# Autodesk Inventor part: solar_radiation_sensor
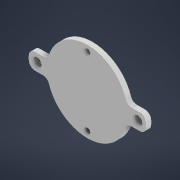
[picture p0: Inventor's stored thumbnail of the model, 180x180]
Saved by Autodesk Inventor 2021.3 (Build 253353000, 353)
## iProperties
Created: 2022-08
Part Number: solar_radiation_sensor
Material: Generisch
Document SubType Name: Modeling
Designer: markus.rampp
Density: 1 g/cm^3
Appearance: Vorgabe
Author: markus.rampp
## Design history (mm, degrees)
sketch "Skizze1"
  geometry: C1 r 40 at (0, 0); C2 r 2.8 at (0, 34); C3 r 2.8 at (0, -34); 1 further point
  constraints: 3 centre point, 2 vertical alignment, 1 coincident
  dimensions: "d20" = 80 diameter of C1; "d21" = 5.6 diameter of C2; "d22" = 5.6 diameter of C3 (= d21); "d23" = 68 distance of C3.centre C2.centre; "d24" = 34 distance of C1.centre C3.centre (= 0.5 x d23)
extrude "Extrusion1" new body sketch "Skizze1" distance "d8" = 5; taper "d9" = 0 deg
sketch "Skizze2"
  geometry: L1 (-58, 8)-(58, 8); L2 (58, 8)-(58, -8); L3 (58, -8)-(-58, -8); L4 (-58, -8)-(-58, 8); C1 r 4.5 at (-50, 0); C2 r 4.5 at (50, 0); C3 r 7 at (-50, 0); 1 further point
  constraints: 8 end point, 3 centre point, 2 horizontal alignment, 2 parallel, 1 coincident, 1 horizontal, 1 perpendicular
  dimensions: "d25" = 116 distance of L2.end L3.end; "d26" = 16 distance of L1.end L2.end; "d27" = 8 distance from line of point (0, 0) L1 (= 0.5 x d26); "d28" = 58 distance from line of L2 point (0, 0) (= 0.5 x d25); "d29" = 9 diameter of C1; "d30" = 9 diameter of C2; "d31" = 100 distance of C2.centre C1.centre; "d32" = 50 distance of C2.centre point (0, 0) (= 0.5 x d31); "d33" = 14 diameter of C3
extrude "Extrusion2" join sketch "Skizze2" distance "d34" = 5; taper "d35" = 0 deg
fillet "Rundung3" dims "d36" = 6
node "Volumenkörper1"
